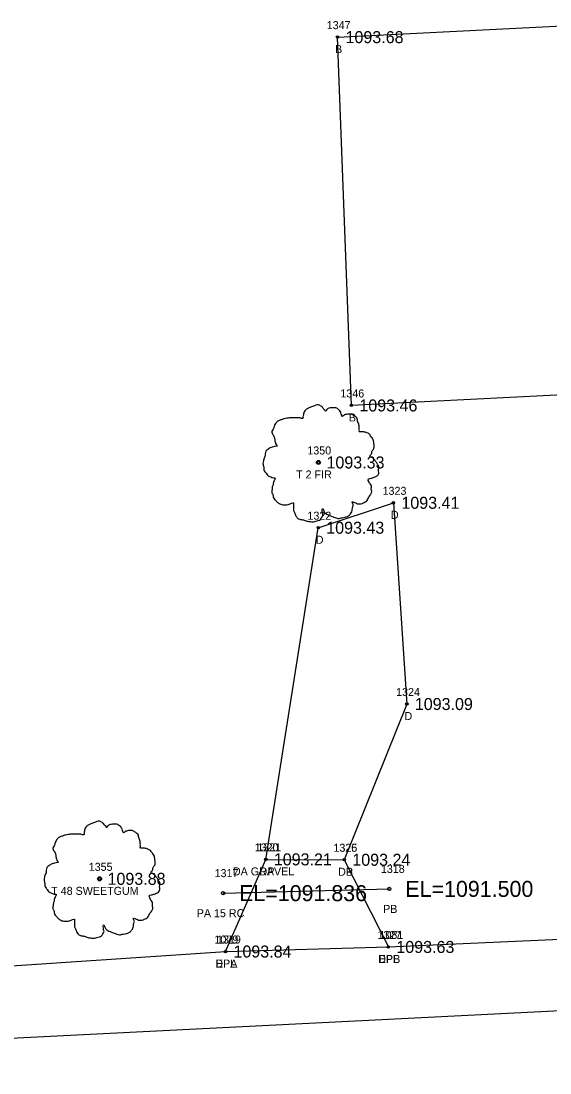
# Model space of a CAD drawing. Extents: x 1539151 to 1541799, y 1198646 to 1201165.
# Drawn here: x 1539723.1 to 1539789.2, y 1199362.5 to 1199493.8 of the extents above; entities that cross this region are included whole.
import ezdxf

# ---------------------------------------------------------------- set-up
doc = ezdxf.new("R2010")
doc.units = 0
for name, color, linetype in [('RD_EX_Bldg', 7, 'Continuous'), ('RD_EX_Bldg_txCode', 7, 'Continuous'), ('RD_EX_DR_Pipe', 7, 'Continuous'), ('RD_EX_DR_Pipe_txCode', 7, 'Continuous'), ('RD_EX_Driveway', 7, 'Continuous'), ('RD_EX_Driveway_txCode', 7, 'Continuous'), ('RD_EX_Road', 7, 'Continuous'), ('RD_EX_Road_txCode', 7, 'Continuous'), ('RD_EX_TX_Bldg_ELEV', 7, 'Continuous'), ('RD_EX_TX_Driveway_ELEV', 7, 'Continuous'), ('RD_EX_TX_Road_ELEV', 7, 'Continuous'), ('RD_EX_TX_VEG_ELEV', 7, 'Continuous'), ('RD_EX_VEG', 7, 'Continuous'), ('RD_EX_VEG_txCode', 7, 'Continuous'), ('RD_HC_Cl', 7, 'Continuous'), ('RD_SMD_Locator', 7, 'Continuous'), ('RD_TX_Pipe_ElevEX', 7, 'Continuous')]:
    doc.layers.add(name, color=color, linetype=linetype)

msp = doc.modelspace()

# ---------------------------------------------------------------- linework, layer by layer
at = {"layer": 'RD_EX_Bldg'}
msp.add_lwpolyline([(1539794.17, 1199447.33), (1539764.43, 1199445.82), (1539762.7, 1199491.82), (1539792.43, 1199493.32), (1539794.17, 1199447.33)], dxfattribs=at)
at = {"layer": 'RD_EX_DR_Pipe'}
msp.add_line((1539748.4, 1199384.91), (1539769.18, 1199385.44), dxfattribs=at)
at = {"layer": 'RD_EX_Driveway'}
for points in [[(1539753.74, 1199389.13), (1539760.29, 1199430.55), (1539769.68, 1199433.66), (1539771.36, 1199408.53), (1539763.55, 1199389.08)], [(1539748.7, 1199377.62), (1539753.74, 1199389.13), (1539763.55, 1199389.08), (1539769.05, 1199378.19)]]:
    msp.add_lwpolyline(points, dxfattribs=at)
at = {"layer": 'RD_EX_Road'}
msp.add_lwpolyline([(1539428.76, 1199454.93), (1539416.46, 1199395.23), (1539420.91, 1199377.84), (1539428.29, 1199368.53), (1539440.24, 1199363.06), (1539462.84, 1199364.11), (1539506.12, 1199366.59), (1539554.03, 1199368.02), (1539606.53, 1199370.48), (1539651.89, 1199372.76), (1539672.94, 1199372.91), (1539707.02, 1199374.85), (1539748.7, 1199377.62), (1539769.05, 1199378.19), (1539812.94, 1199380.16), (1539830.48, 1199381.23), (1539857.01, 1199382.87), (1539908.22, 1199385.45), (1539955.82, 1199389.74), (1539996.13, 1199397.4), (1540037.85, 1199410.51), (1540050.26, 1199415.61), (1540093.12, 1199444.78)], dxfattribs=at)
at = {"layer": 'RD_EX_VEG'}
for centre, radius in [((1539760.32, 1199438.7), 0.25), ((1539760.31, 1199438.68), 0.0001), ((1539732.96, 1199386.7), 0.25), ((1539732.95, 1199386.68), 0.0001)]:
    msp.add_circle(centre, radius, dxfattribs=at)
for points in [[(1539760.45, 1199445.87), (1539760.15, 1199445.89), (1539759.83, 1199445.79), (1539759.58, 1199445.69), (1539759.35, 1199445.62), (1539759.13, 1199445.52), (1539758.83, 1199445.34), (1539758.6, 1199445.14), (1539758.48, 1199444.89), (1539758.43, 1199444.67), (1539758.38, 1199444.39), (1539758.38, 1199444.22), (1539758.25, 1199444.19), (1539758.1, 1199444.22), (1539757.85, 1199444.29), (1539757.6, 1199444.29), (1539757.35, 1199444.29), (1539757, 1199444.27), (1539756.65, 1199444.27), (1539756.38, 1199444.22), (1539756.05, 1199444.17), (1539755.68, 1199444.04), (1539755.33, 1199443.92), (1539755.03, 1199443.67), (1539754.78, 1199443.19), (1539754.65, 1199442.84), (1539754.5, 1199442.59), (1539754.65, 1199442.14), (1539754.83, 1199441.79), (1539754.85, 1199441.59), (1539754.93, 1199441.17), (1539755.03, 1199440.94), (1539755.15, 1199440.74), (1539755.08, 1199440.72), (1539754.7, 1199440.67), (1539754.4, 1199440.57), (1539753.98, 1199440.34), (1539753.75, 1199440.12), (1539753.65, 1199439.79), (1539753.63, 1199439.44), (1539753.53, 1199439.24), (1539753.45, 1199438.97), (1539753.43, 1199438.89), (1539753.38, 1199438.57), (1539753.48, 1199438.12), (1539753.5, 1199437.77), (1539753.63, 1199437.54), (1539753.78, 1199437.37), (1539753.95, 1199437.12), (1539754.35, 1199436.9), (1539754.68, 1199436.8), (1539754.88, 1199436.77), (1539754.7, 1199436.27), (1539754.65, 1199435.92), (1539754.53, 1199435.52), (1539754.53, 1199435.45), (1539754.48, 1199434.97), (1539754.63, 1199434.65), (1539754.7, 1199434.27), (1539754.88, 1199434.05), (1539755.15, 1199433.75), (1539755.48, 1199433.52), (1539755.98, 1199433.4), (1539756.38, 1199433.42), (1539756.95, 1199433.6), (1539757.2, 1199433.67), (1539757.18, 1199433.5), (1539757.2, 1199433.12), (1539757.2, 1199432.7), (1539757.35, 1199432.37), (1539757.45, 1199432.1), (1539757.6, 1199431.85), (1539757.93, 1199431.62), (1539758.33, 1199431.55), (1539758.75, 1199431.4), (1539759.2, 1199431.32), (1539759.7, 1199431.3), (1539760.3, 1199431.45), (1539760.57, 1199431.57), (1539760.67, 1199431.75), (1539760.87, 1199432.12), (1539760.82, 1199432.35), (1539760.85, 1199432.95), (1539760.95, 1199432.77), (1539761.12, 1199432.42), (1539761.62, 1199432.12), (1539762.02, 1199431.95), (1539762.5, 1199431.8), (1539762.8, 1199431.72), (1539763.27, 1199431.8), (1539763.65, 1199431.87), (1539764.02, 1199432), (1539764.32, 1199432.27), (1539764.5, 1199432.55), (1539764.55, 1199432.82), (1539764.62, 1199433.2), (1539764.67, 1199433.37)], [(1539764.67, 1199433.37), (1539764.6, 1199433.55), (1539764.55, 1199433.8), (1539764.62, 1199433.77), (1539764.8, 1199433.72), (1539765.07, 1199433.6), (1539765.3, 1199433.52), (1539765.62, 1199433.55), (1539765.9, 1199433.65), (1539766.35, 1199433.92), (1539766.62, 1199434.4), (1539766.9, 1199434.8), (1539766.97, 1199435.12), (1539766.92, 1199435.35), (1539766.9, 1199435.85), (1539766.7, 1199436.1), (1539766.65, 1199436.22), (1539766.55, 1199436.62), (1539766.62, 1199436.67), (1539766.9, 1199436.72), (1539767.27, 1199436.85), (1539767.55, 1199436.97), (1539767.77, 1199437.14), (1539767.85, 1199437.37), (1539767.82, 1199437.77), (1539767.87, 1199438.17), (1539767.8, 1199438.32), (1539767.7, 1199438.47), (1539767.62, 1199438.67), (1539767.47, 1199438.82), (1539767.37, 1199438.97), (1539767.27, 1199439.07), (1539767.15, 1199439.22), (1539766.97, 1199439.34), (1539766.82, 1199439.39), (1539766.77, 1199439.54), (1539766.92, 1199439.74), (1539766.97, 1199439.84), (1539767, 1199440.07), (1539767.22, 1199440.42), (1539767.27, 1199440.82), (1539767.22, 1199441.24), (1539767.17, 1199441.52), (1539767.02, 1199441.79), (1539766.82, 1199442.04), (1539766.7, 1199442.22), (1539766.52, 1199442.34), (1539766.2, 1199442.47), (1539765.95, 1199442.52), (1539765.6, 1199442.52), (1539765.4, 1199442.57), (1539765.42, 1199442.62), (1539765.42, 1199442.77), (1539765.42, 1199443.04), (1539765.35, 1199443.49), (1539765.2, 1199443.99), (1539765.2, 1199444.02), (1539765.1, 1199444.27), (1539764.87, 1199444.47), (1539764.7, 1199444.57), (1539764.5, 1199444.69), (1539764.25, 1199444.72), (1539763.95, 1199444.72), (1539763.67, 1199444.67), (1539763.47, 1199444.57), (1539763.3, 1199444.44), (1539763.22, 1199444.59), (1539763.12, 1199444.89), (1539763.07, 1199445.04), (1539762.92, 1199445.22), (1539762.7, 1199445.42), (1539762.25, 1199445.54), (1539761.62, 1199445.47), (1539761.32, 1199445.27), (1539761.17, 1199445.09), (1539761.12, 1199445.22), (1539760.92, 1199445.42), (1539760.82, 1199445.59), (1539760.65, 1199445.72), (1539760.5, 1199445.82), (1539760.4, 1199445.87)], [(1539733.09, 1199393.87), (1539732.79, 1199393.89), (1539732.47, 1199393.79), (1539732.22, 1199393.69), (1539731.99, 1199393.62), (1539731.77, 1199393.52), (1539731.47, 1199393.34), (1539731.24, 1199393.14), (1539731.12, 1199392.89), (1539731.07, 1199392.67), (1539731.02, 1199392.39), (1539731.02, 1199392.22), (1539730.89, 1199392.19), (1539730.74, 1199392.22), (1539730.49, 1199392.29), (1539730.24, 1199392.29), (1539729.99, 1199392.29), (1539729.64, 1199392.27), (1539729.29, 1199392.27), (1539729.02, 1199392.22), (1539728.69, 1199392.17), (1539728.32, 1199392.04), (1539727.97, 1199391.92), (1539727.67, 1199391.67), (1539727.42, 1199391.19), (1539727.29, 1199390.84), (1539727.14, 1199390.59), (1539727.29, 1199390.14), (1539727.47, 1199389.79), (1539727.49, 1199389.59), (1539727.57, 1199389.17), (1539727.67, 1199388.94), (1539727.79, 1199388.74), (1539727.72, 1199388.72), (1539727.34, 1199388.67), (1539727.04, 1199388.57), (1539726.62, 1199388.34), (1539726.39, 1199388.12), (1539726.29, 1199387.79), (1539726.27, 1199387.44), (1539726.17, 1199387.24), (1539726.09, 1199386.97), (1539726.07, 1199386.89), (1539726.02, 1199386.57), (1539726.12, 1199386.12), (1539726.14, 1199385.77), (1539726.27, 1199385.54), (1539726.42, 1199385.37), (1539726.59, 1199385.12), (1539726.99, 1199384.89), (1539727.32, 1199384.79), (1539727.52, 1199384.77), (1539727.34, 1199384.27), (1539727.29, 1199383.92), (1539727.17, 1199383.52), (1539727.17, 1199383.44), (1539727.12, 1199382.97), (1539727.27, 1199382.64), (1539727.34, 1199382.27), (1539727.52, 1199382.05), (1539727.79, 1199381.75), (1539728.12, 1199381.52), (1539728.62, 1199381.4), (1539729.02, 1199381.42), (1539729.59, 1199381.6), (1539729.84, 1199381.67), (1539729.82, 1199381.5), (1539729.84, 1199381.12), (1539729.84, 1199380.7), (1539729.99, 1199380.37), (1539730.09, 1199380.1), (1539730.24, 1199379.85), (1539730.57, 1199379.62), (1539730.97, 1199379.55), (1539731.39, 1199379.4), (1539731.84, 1199379.32), (1539732.34, 1199379.3), (1539732.94, 1199379.45), (1539733.22, 1199379.57), (1539733.32, 1199379.75), (1539733.52, 1199380.12), (1539733.47, 1199380.35), (1539733.49, 1199380.95), (1539733.59, 1199380.77), (1539733.77, 1199380.42), (1539734.27, 1199380.12), (1539734.67, 1199379.95), (1539735.14, 1199379.8), (1539735.44, 1199379.72), (1539735.92, 1199379.8), (1539736.29, 1199379.87), (1539736.67, 1199380), (1539736.97, 1199380.27), (1539737.14, 1199380.55), (1539737.19, 1199380.82), (1539737.26, 1199381.2), (1539737.31, 1199381.37)], [(1539737.31, 1199381.37), (1539737.24, 1199381.55), (1539737.19, 1199381.8), (1539737.26, 1199381.77), (1539737.44, 1199381.72), (1539737.71, 1199381.6), (1539737.94, 1199381.52), (1539738.26, 1199381.55), (1539738.54, 1199381.65), (1539738.99, 1199381.92), (1539739.26, 1199382.4), (1539739.54, 1199382.79), (1539739.61, 1199383.12), (1539739.56, 1199383.34), (1539739.54, 1199383.84), (1539739.34, 1199384.09), (1539739.29, 1199384.22), (1539739.19, 1199384.62), (1539739.26, 1199384.67), (1539739.54, 1199384.72), (1539739.91, 1199384.84), (1539740.19, 1199384.97), (1539740.41, 1199385.14), (1539740.49, 1199385.37), (1539740.46, 1199385.77), (1539740.51, 1199386.17), (1539740.44, 1199386.32), (1539740.34, 1199386.47), (1539740.26, 1199386.67), (1539740.11, 1199386.82), (1539740.01, 1199386.97), (1539739.91, 1199387.07), (1539739.79, 1199387.22), (1539739.61, 1199387.34), (1539739.46, 1199387.39), (1539739.41, 1199387.54), (1539739.56, 1199387.74), (1539739.61, 1199387.84), (1539739.64, 1199388.07), (1539739.86, 1199388.42), (1539739.91, 1199388.82), (1539739.86, 1199389.24), (1539739.81, 1199389.52), (1539739.66, 1199389.79), (1539739.46, 1199390.04), (1539739.34, 1199390.22), (1539739.16, 1199390.34), (1539738.84, 1199390.47), (1539738.59, 1199390.52), (1539738.24, 1199390.52), (1539738.04, 1199390.57), (1539738.06, 1199390.62), (1539738.06, 1199390.77), (1539738.06, 1199391.04), (1539737.99, 1199391.49), (1539737.84, 1199391.99), (1539737.84, 1199392.02), (1539737.74, 1199392.27), (1539737.51, 1199392.47), (1539737.34, 1199392.57), (1539737.14, 1199392.69), (1539736.89, 1199392.72), (1539736.59, 1199392.72), (1539736.32, 1199392.67), (1539736.12, 1199392.57), (1539735.94, 1199392.44), (1539735.87, 1199392.59), (1539735.77, 1199392.89), (1539735.72, 1199393.04), (1539735.57, 1199393.22), (1539735.34, 1199393.42), (1539734.89, 1199393.54), (1539734.27, 1199393.47), (1539733.97, 1199393.27), (1539733.82, 1199393.09), (1539733.77, 1199393.22), (1539733.57, 1199393.42), (1539733.47, 1199393.59), (1539733.29, 1199393.72), (1539733.14, 1199393.82), (1539733.04, 1199393.87)]]:
    msp.add_spline(points, degree=3, dxfattribs=at)
at = {"layer": 'RD_HC_Cl'}
msp.add_line((1539393.53, 1199350.4), (1539900.86, 1199375.77), dxfattribs=at)
at = {"layer": 'RD_SMD_Locator'}
for centre, radius in [((1539762.7, 1199491.82), 0.15), ((1539764.43, 1199445.82), 0.15), ((1539760.32, 1199438.7), 0.15), ((1539769.68, 1199433.66), 0.15), ((1539760.29, 1199430.55), 0.15), ((1539771.36, 1199408.53), 0.15), ((1539753.74, 1199389.13), 0.15), ((1539753.74, 1199389.13), 0.15), ((1539763.55, 1199389.08), 0.15), ((1539763.55, 1199389.08), 0.15), ((1539732.96, 1199386.7), 0.15), ((1539748.4, 1199384.91), 0.2), ((1539769.18, 1199385.44), 0.2), ((1539748.7, 1199377.62), 0.15), ((1539748.7, 1199377.62), 0.15), ((1539769.05, 1199378.19), 0.15), ((1539769.05, 1199378.19), 0.15)]:
    msp.add_circle(centre, radius, dxfattribs=at)

# ---------------------------------------------------------------- texts
at = {"layer": 'RD_EX_Bldg_txCode'}
for s, p in [('1347', (1539761.35, 1199492.82)), ('B', (1539762.39, 1199489.82)), ('1346', (1539763.06, 1199446.82)), ('B', (1539764.12, 1199443.82))]:
    msp.add_text(s, height=1, dxfattribs=at).set_placement(p)
at = {"layer": 'RD_EX_DR_Pipe_txCode'}
for s, p in [('1317', (1539747.34, 1199386.91)), ('1318', (1539768.12, 1199387.44)), ('PA 15 RC', (1539745.11, 1199381.91)), ('PB', (1539768.4, 1199382.44))]:
    msp.add_text(s, height=1, dxfattribs=at).set_placement(p)
at = {"layer": 'RD_EX_Driveway_txCode'}
for s, p in [('1323', (1539768.33, 1199434.66)), ('1322', (1539758.94, 1199431.55)), ('D', (1539769.37, 1199431.66)), ('D', (1539759.98, 1199428.55)), ('1324', (1539770.02, 1199409.53)), ('D', (1539771.06, 1199406.53)), ('1320', (1539752.35, 1199390.13)), ('1321', (1539752.67, 1199390.13)), ('1326', (1539762.18, 1199390.08)), ('1325', (1539762.2, 1199390.08)), ('DA GRAVEL', (1539749.63, 1199387.13)), ('DP', (1539752.96, 1199387.13)), ('DB', (1539762.77, 1199387.08)), ('DP', (1539762.77, 1199387.08)), ('1327', (1539767.7, 1199379.19)), ('1319', (1539747.64, 1199378.62)), ('DPA', (1539747.43, 1199375.62)), ('DPB', (1539767.79, 1199376.19))]:
    msp.add_text(s, height=1, dxfattribs=at).set_placement(p)
at = {"layer": 'RD_EX_Road_txCode'}
for s, p in [('1081', (1539767.94, 1199379.19)), ('1079', (1539747.32, 1199378.62)), ('EPL', (1539747.5, 1199375.62)), ('EPL', (1539767.84, 1199376.19))]:
    msp.add_text(s, height=1, dxfattribs=at).set_placement(p)
at = {"layer": 'RD_EX_TX_Bldg_ELEV'}
for s, p in [('1093.68', (1539763.7, 1199491.07)), ('1093.46', (1539765.43, 1199445.07))]:
    msp.add_text(s, height=1.5, dxfattribs=at).set_placement(p)
at = {"layer": 'RD_EX_TX_Driveway_ELEV'}
for s, p in [('1093.41', (1539770.68, 1199432.91)), ('1093.43', (1539761.29, 1199429.8)), ('1093.09', (1539772.36, 1199407.78)), ('1093.21', (1539754.74, 1199388.38)), ('1093.21', (1539754.74, 1199388.38)), ('1093.24', (1539764.55, 1199388.33)), ('1093.24', (1539764.55, 1199388.33)), ('1093.63', (1539770.05, 1199377.44)), ('1093.84', (1539749.7, 1199376.87))]:
    msp.add_text(s, height=1.5, dxfattribs=at).set_placement(p)
at = {"layer": 'RD_EX_TX_Road_ELEV'}
for s, p in [('1093.63', (1539770.05, 1199377.44)), ('1093.84', (1539749.7, 1199376.87))]:
    msp.add_text(s, height=1.5, dxfattribs=at).set_placement(p)
at = {"layer": 'RD_EX_TX_VEG_ELEV'}
for s, p in [('1093.33', (1539761.32, 1199437.95)), ('1093.88', (1539733.96, 1199385.95))]:
    msp.add_text(s, height=1.5, dxfattribs=at).set_placement(p)
at = {"layer": 'RD_EX_VEG_txCode'}
for s, p in [('1350', (1539758.93, 1199439.7)), ('T 2 FIR', (1539757.52, 1199436.7)), ('1355', (1539731.61, 1199387.7)), ('T 48 SWEETGUM', (1539726.92, 1199384.7))]:
    msp.add_text(s, height=1, dxfattribs=at).set_placement(p)
at = {"layer": 'RD_TX_Pipe_ElevEX'}
for s, p in [('EL=1091.500', (1539771.18, 1199384.44)), ('EL=1091.836', (1539750.4, 1199383.91))]:
    msp.add_text(s, height=2, dxfattribs=at).set_placement(p)

doc.saveas('drawing.dxf')
